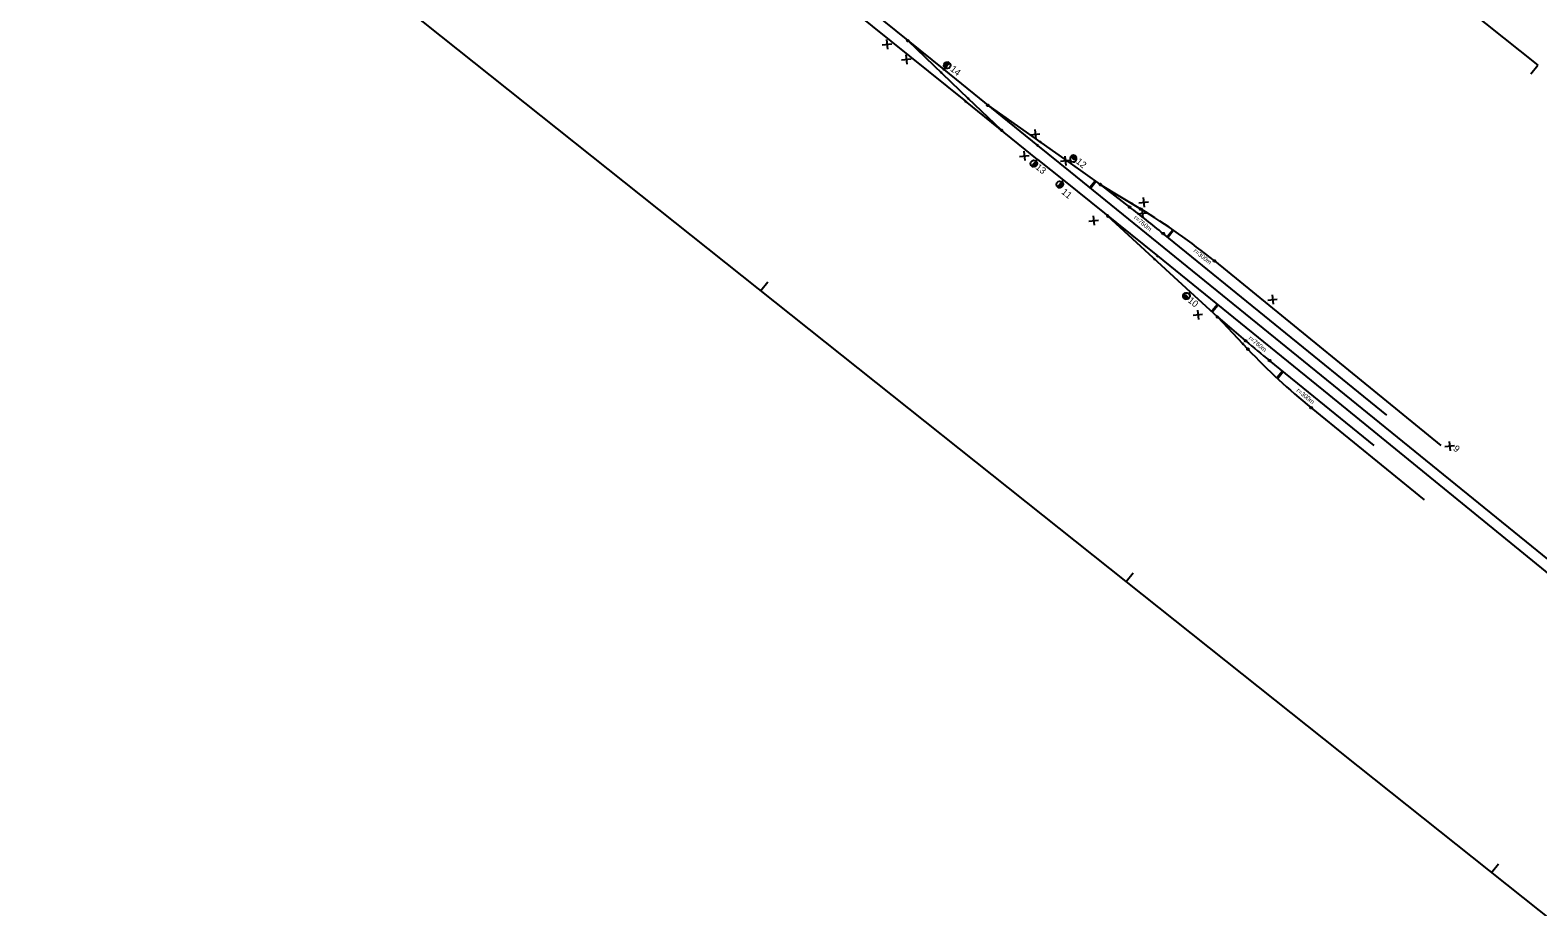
# Model space of a CAD drawing. Extents: x -481120 to -479270, y -1317564 to -1316014.
# Drawn here: x -481120 to -480442, y -1316785 to -1316391 of the extents above; entities that cross this region are included whole.
import ezdxf

# ---------------------------------------------------------------- set-up
doc = ezdxf.new("R2010")
doc.units = 0
for name, color, linetype in [('kolaj s', 7, 'Continuous'), ('Level 61', 7, 'Continuous'), ('popis 25', 7, 'Continuous'), ('popis 35', 7, 'Continuous')]:
    doc.layers.add(name, color=color, linetype=linetype)

msp = doc.modelspace()

# ---------------------------------------------------------------- linework, layer by layer
at = {"layer": 'kolaj s'}
for p, q in [((-480888.64, -1316270.51), (-480699.16, -1316423.18)), ((-480741.34, -1316382.82), (-480709, -1316408.98)), ((-480725.17, -1316395.9), (-480725.17, -1316395.9)), ((-480725.17, -1316395.9), (-480698.02, -1316421.88)), ((-480708.7, -1316408.59), (-480709.3, -1316409.38)), ((-480709, -1316408.98), (-480709, -1316408.98)), ((-480709, -1316408.98), (-480666.85, -1316443.08)), ((-480709.8, -1316409.92), (-480710.49, -1316410.64)), ((-480710.14, -1316410.28), (-480710.14, -1316410.28)), ((-480699.47, -1316423.57), (-480698.85, -1316422.79)), ((-480698.36, -1316422.24), (-480697.67, -1316421.52)), ((-480682.99, -1316436.26), (-480698.02, -1316421.88)), ((-480698.02, -1316421.88), (-480698.02, -1316421.88)), ((-480666.82, -1316449.34), (-480699.16, -1316423.18)), ((-480699.16, -1316423.18), (-480699.16, -1316423.18)), ((-480689.2, -1316425), (-480689.2, -1316425)), ((-480689.2, -1316425), (-480652.2, -1316451.04)), ((-480682.99, -1316436.26), (-480682.99, -1316436.26)), ((-480666.54, -1316442.69), (-480667.17, -1316443.47)), ((-480666.85, -1316443.08), (-480652.11, -1316455)), ((-480666.85, -1316443.08), (-480666.85, -1316443.08)), ((-480665.4, -1316441.14), (-480665.98, -1316441.95)), ((-480665.69, -1316441.54), (-480665.69, -1316441.54)), ((-480666.82, -1316449.34), (-480655.14, -1316458.74)), ((-480652.2, -1316451.04), (-480638.61, -1316460.6)), ((-480652.11, -1316455), (-480403.35, -1316656.97)), ((-480655.14, -1316458.74), (-480612.91, -1316492.74)), ((-480638.61, -1316460.6), (-480638.61, -1316460.6)), ((-480638.61, -1316460.6), (-480620.49, -1316471.62)), ((-480638.61, -1316460.6), (-480625.45, -1316470.75)), ((-480625.15, -1316470.35), (-480625.76, -1316471.14)), ((-480624.15, -1316468.81), (-480624.67, -1316469.66)), ((-480624.41, -1316469.23), (-480624.41, -1316469.23)), ((-480635.3, -1316474.72), (-480598.2, -1316508.93)), ((-480635.3, -1316474.72), (-480635.3, -1316474.72)), ((-480625.45, -1316470.75), (-480625.45, -1316470.75)), ((-480625.45, -1316470.75), (-480625.45, -1316470.75)), ((-480620.49, -1316471.62), (-480620.49, -1316471.62)), ((-480610.31, -1316482.74), (-480509.95, -1316564.28)), ((-480610.31, -1316482.74), (-480610.31, -1316482.74)), ((-480614.51, -1316494.57), (-480613.83, -1316493.83)), ((-480614.17, -1316494.2), (-480614.17, -1316494.2)), ((-480613.22, -1316493.13), (-480612.6, -1316492.35)), ((-480612.91, -1316492.74), (-480612.91, -1316492.74)), ((-480612.91, -1316492.74), (-480535.94, -1316555.28)), ((-480587.3, -1316495.01), (-480485.45, -1316578.03)), ((-480587.3, -1316495.01), (-480587.3, -1316495.01)), ((-480598.2, -1316508.93), (-480585.98, -1316520.2)), ((-480585.98, -1316520.19), (-480585.98, -1316520.19)), ((-480585.98, -1316520.19), (-480572.26, -1316534.66)), ((-480585.98, -1316520.19), (-480573.29, -1316530.91)), ((-480572.96, -1316530.53), (-480573.61, -1316531.29)), ((-480573.29, -1316530.91), (-480573.29, -1316530.91)), ((-480573.28, -1316530.92), (-480573.28, -1316530.92)), ((-480574.19, -1316531.9), (-480574.91, -1316532.59)), ((-480574.19, -1316531.9), (-480574.91, -1316532.59)), ((-480574.55, -1316532.25), (-480574.55, -1316532.25)), ((-480574.55, -1316532.25), (-480574.55, -1316532.25)), ((-480572.26, -1316534.66), (-480572.26, -1316534.66)), ((-480515.51, -1316578.06), (-480562.53, -1316539.83)), ((-480562.53, -1316539.83), (-480562.53, -1316539.83)), ((-480535.94, -1316555.28), (-480406.36, -1316660.81)), ((-480543.8, -1316561.02), (-480492.95, -1316602.35)), ((-480543.8, -1316561.02), (-480543.8, -1316561.02))]:
    msp.add_line(p, q, dxfattribs=at)
for points in [[(-480724.86, -1316396.16), (-480725.23, -1316396.3), (-480725.54, -1316396.05), (-480725.48, -1316395.65), (-480725.1, -1316395.51), (-480724.79, -1316395.76), (-480724.86, -1316396.16)], [(-480689.43, -1316425.33), (-480689.6, -1316424.97), (-480689.37, -1316424.64), (-480688.97, -1316424.68), (-480688.8, -1316425.04), (-480689.03, -1316425.37), (-480689.43, -1316425.33)], [(-480683.3, -1316436.01), (-480682.93, -1316435.87), (-480682.62, -1316436.12), (-480682.68, -1316436.51), (-480683.06, -1316436.65), (-480683.36, -1316436.4), (-480683.3, -1316436.01)], [(-480638.29, -1316460.84), (-480638.66, -1316461), (-480638.98, -1316460.75), (-480638.93, -1316460.36), (-480638.56, -1316460.2), (-480638.24, -1316460.45), (-480638.29, -1316460.84)], [(-480625.2, -1316470.44), (-480625.05, -1316470.81), (-480625.29, -1316471.12), (-480625.69, -1316471.07), (-480625.84, -1316470.7), (-480625.6, -1316470.38), (-480625.2, -1316470.44)], [(-480635.03, -1316474.42), (-480635.42, -1316474.34), (-480635.69, -1316474.63), (-480635.57, -1316475.01), (-480635.18, -1316475.1), (-480634.91, -1316474.81), (-480635.03, -1316474.42)], [(-480620.28, -1316471.28), (-480620.09, -1316471.62), (-480620.3, -1316471.96), (-480620.7, -1316471.96), (-480620.89, -1316471.61), (-480620.69, -1316471.27), (-480620.28, -1316471.28)], [(-480610.56, -1316483.05), (-480610.7, -1316482.68), (-480610.45, -1316482.37), (-480610.05, -1316482.43), (-480609.91, -1316482.8), (-480610.16, -1316483.11), (-480610.56, -1316483.05)], [(-480587.55, -1316495.32), (-480587.7, -1316494.95), (-480587.44, -1316494.64), (-480587.05, -1316494.7), (-480586.91, -1316495.07), (-480587.16, -1316495.38), (-480587.55, -1316495.32)], [(-480585.68, -1316520.45), (-480586.05, -1316520.58), (-480586.36, -1316520.33), (-480586.29, -1316519.93), (-480585.91, -1316519.8), (-480585.61, -1316520.06), (-480585.68, -1316520.45)], [(-480573.02, -1316530.61), (-480572.89, -1316530.99), (-480573.14, -1316531.29), (-480573.54, -1316531.22), (-480573.67, -1316530.84), (-480573.42, -1316530.54), (-480573.02, -1316530.61)], [(-480571.97, -1316534.39), (-480571.88, -1316534.77), (-480572.16, -1316535.05), (-480572.55, -1316534.94), (-480572.64, -1316534.55), (-480572.35, -1316534.27), (-480571.97, -1316534.39)], [(-480562.78, -1316540.14), (-480562.92, -1316539.76), (-480562.67, -1316539.45), (-480562.27, -1316539.52), (-480562.13, -1316539.89), (-480562.38, -1316540.2), (-480562.78, -1316540.14)], [(-480544.05, -1316561.33), (-480544.2, -1316560.96), (-480543.95, -1316560.65), (-480543.55, -1316560.71), (-480543.41, -1316561.08), (-480543.66, -1316561.39), (-480544.05, -1316561.33)]]:
    msp.add_lwpolyline(points, dxfattribs=at)
for centre, radius, start, end in [((-481089.57, -1317072.58), 760, 50.90503, 52.36083), ((-480776.33, -1316727.97), 300, 50.94386, 58.70492), ((-480083.02, -1315950.19), 760, 229.82799, 230.88077), ((-480354.59, -1316328.21), 300, 223.48502, 230.89789)]:
    msp.add_arc(centre, radius, start, end, dxfattribs=at)
at = {"layer": 'Level 61'}
for p, q in [((-480934.65, -1316014.34), (-480441.9, -1316406.9)), ((-480626.96, -1316639.2), (-481119.71, -1316246.64)), ((-480445.02, -1316410.81), (-480441.9, -1316406.9)), ((-480791.21, -1316508.34), (-480788.1, -1316504.43)), ((-480626.96, -1316639.2), (-480623.85, -1316635.28)), ((-479477.22, -1317555.16), (-480626.96, -1316639.2)), ((-480462.72, -1316770.05), (-480459.6, -1316766.14))]:
    msp.add_line(p, q, dxfattribs=at)
at = {"layer": 'popis 25'}
for p, q in [((-480641.07, -1316459.25), (-480643.26, -1316461.98)), ((-480640.71, -1316459.54), (-480642.9, -1316462.27)), ((-480606.21, -1316481.24), (-480608.4, -1316483.97)), ((-480605.85, -1316481.52), (-480608.04, -1316484.25)), ((-480586.12, -1316514.77), (-480588.31, -1316517.5)), ((-480585.77, -1316515.06), (-480587.96, -1316517.79)), ((-480556.86, -1316544.72), (-480559.05, -1316547.45)), ((-480556.5, -1316545.01), (-480558.69, -1316547.74))]:
    msp.add_line(p, q, dxfattribs=at)
at = {"layer": 'popis 35'}
for p, q in [((-480734.73, -1316395.44), (-480734.29, -1316399.69)), ((-480736.64, -1316397.78), (-480732.38, -1316397.34)), ((-480726.03, -1316402.28), (-480725.58, -1316406.53)), ((-480727.93, -1316404.62), (-480723.68, -1316404.18)), ((-480709, -1316408.98), (-480706.51, -1316405.91)), ((-480709, -1316408.98), (-480709, -1316408.98)), ((-480668.07, -1316435.92), (-480667.63, -1316440.17)), ((-480669.98, -1316438.26), (-480665.73, -1316437.82)), ((-480674.87, -1316448), (-480670.61, -1316447.56)), ((-480672.96, -1316445.65), (-480672.52, -1316449.9)), ((-480666.82, -1316449.34), (-480669.46, -1316452.28)), ((-480666.82, -1316449.34), (-480666.82, -1316449.34)), ((-480656.52, -1316450.18), (-480652.27, -1316449.74)), ((-480654.61, -1316447.83), (-480654.17, -1316452.09)), ((-480651.99, -1316448.13), (-480652.23, -1316448.82)), ((-480652.23, -1316448.82), (-480652.14, -1316449.57)), ((-480652.2, -1316451.04), (-480651.62, -1316450.22)), ((-480652.14, -1316449.57), (-480651.62, -1316450.22)), ((-480651.38, -1316447.65), (-480651.99, -1316448.13)), ((-480651.62, -1316450.22), (-480650.84, -1316450.5)), ((-480650.68, -1316447.48), (-480651.38, -1316447.65)), ((-480651.37, -1316448.3), (-480650.98, -1316447.74)), ((-480650.62, -1316447.75), (-480651.23, -1316448.61)), ((-480651.03, -1316448.86), (-480650.32, -1316447.84)), ((-480650.98, -1316447.74), (-480650.62, -1316447.75)), ((-480649.9, -1316447.77), (-480650.81, -1316449.06)), ((-480649.9, -1316447.77), (-480650.81, -1316449.06)), ((-480649.9, -1316447.77), (-480650.68, -1316447.48)), ((-480650.54, -1316449.21), (-480649.82, -1316448.19)), ((-480650.32, -1316447.84), (-480649.9, -1316447.77)), ((-480649.64, -1316448.44), (-480650.24, -1316449.3)), ((-480650.09, -1316450.36), (-480649.53, -1316449.86)), ((-480649.37, -1316448.42), (-480649.9, -1316447.77)), ((-480649.9, -1316447.77), (-480649.37, -1316448.4)), ((-480649.82, -1316448.19), (-480649.9, -1316447.77)), ((-480649.9, -1316449.33), (-480649.51, -1316448.78)), ((-480649.51, -1316448.78), (-480649.64, -1316448.44)), ((-480649.53, -1316449.86), (-480649.25, -1316449.14)), ((-480649.25, -1316449.14), (-480649.37, -1316448.42)), ((-480650.84, -1316450.5), (-480650.09, -1316450.36)), ((-480655.14, -1316458.74), (-480657.78, -1316461.68)), ((-480655.14, -1316458.74), (-480655.14, -1316458.74)), ((-480621.24, -1316468.85), (-480616.98, -1316468.4)), ((-480619.33, -1316466.5), (-480618.89, -1316470.75)), ((-480643.72, -1316477.06), (-480639.47, -1316476.61)), ((-480641.82, -1316474.71), (-480641.38, -1316478.96)), ((-480621.89, -1316473.75), (-480617.64, -1316473.31)), ((-480619.99, -1316471.4), (-480619.54, -1316475.66)), ((-480601.35, -1316511.17), (-480601.34, -1316510.45)), ((-480600.91, -1316511.87), (-480601.35, -1316511.17)), ((-480601.34, -1316510.45), (-480601, -1316509.75)), ((-480600.7, -1316510.32), (-480601.16, -1316510.82)), ((-480601.16, -1316510.82), (-480601.08, -1316511.17)), ((-480601.08, -1316511.17), (-480600.36, -1316510.39)), ((-480601, -1316509.75), (-480600.37, -1316509.37)), ((-480600.08, -1316510.53), (-480600.93, -1316511.44)), ((-480600.91, -1316511.87), (-480599.84, -1316510.71)), ((-480600.91, -1316511.87), (-480599.84, -1316510.71)), ((-480599.64, -1316510.93), (-480600.49, -1316511.85)), ((-480600.37, -1316509.37), (-480599.63, -1316509.29)), ((-480600.2, -1316511.98), (-480599.48, -1316511.21)), ((-480599.63, -1316509.29), (-480598.88, -1316509.66)), ((-480598.88, -1316509.66), (-480598.2, -1316508.93)), ((-480598.88, -1316509.66), (-480598.43, -1316510.37)), ((-480598.42, -1316511.13), (-480598.79, -1316511.78)), ((-480598.43, -1316510.37), (-480598.42, -1316511.13)), ((-480561.41, -1316510.22), (-480560.96, -1316514.47)), ((-480600.93, -1316511.44), (-480600.91, -1316511.87)), ((-480600.49, -1316511.85), (-480600.91, -1316511.87)), ((-480600.16, -1316512.25), (-480600.91, -1316511.87)), ((-480600.91, -1316511.87), (-480600.18, -1316512.25)), ((-480599.84, -1316512.04), (-480600.2, -1316511.98)), ((-480599.43, -1316512.21), (-480600.16, -1316512.25)), ((-480599.38, -1316511.54), (-480599.84, -1316512.04)), ((-480598.79, -1316511.78), (-480599.43, -1316512.21)), ((-480594.96, -1316517.1), (-480594.52, -1316521.35)), ((-480563.31, -1316512.57), (-480559.06, -1316512.12)), ((-480596.87, -1316519.44), (-480592.62, -1316519)), ((-480483.65, -1316578.49), (-480479.39, -1316578.05)), ((-480481.74, -1316576.15), (-480481.3, -1316580.4))]:
    msp.add_line(p, q, dxfattribs=at)
for points in [[(-480706.83, -1316405.66), (-480706.2, -1316406.16), (-480705.93, -1316406.91), (-480706.06, -1316407.65), (-480706.55, -1316408.25), (-480707.27, -1316408.53), (-480708.03, -1316408.42), (-480708.65, -1316407.92), (-480708.92, -1316407.2), (-480708.81, -1316406.44), (-480708.3, -1316405.82), (-480707.58, -1316405.55), (-480706.83, -1316405.66), (-480707.18, -1316405.7), (-480706.79, -1316406.01), (-480706.98, -1316406.25), (-480707.64, -1316405.71), (-480707.98, -1316405.82), (-480707.17, -1316406.48), (-480707.36, -1316406.71), (-480708.25, -1316405.99), (-480708.44, -1316406.22), (-480707.54, -1316406.95), (-480707.73, -1316407.18), (-480708.63, -1316406.46), (-480708.7, -1316406.78), (-480707.92, -1316407.41), (-480708.11, -1316407.65), (-480708.77, -1316407.11), (-480708.69, -1316407.56), (-480708.3, -1316407.88)], [(-480669.17, -1316452.54), (-480669.76, -1316452.01), (-480669.99, -1316451.25), (-480669.84, -1316450.53), (-480669.3, -1316449.93), (-480668.57, -1316449.7), (-480667.82, -1316449.85), (-480667.23, -1316450.39), (-480666.99, -1316451.12), (-480667.16, -1316451.88), (-480667.67, -1316452.46), (-480668.41, -1316452.7), (-480669.17, -1316452.54), (-480668.81, -1316452.53), (-480669.18, -1316452.19), (-480668.98, -1316451.97), (-480668.35, -1316452.54), (-480668.04, -1316452.41), (-480668.78, -1316451.74), (-480668.58, -1316451.52), (-480667.73, -1316452.29), (-480667.53, -1316452.07), (-480668.38, -1316451.3), (-480668.18, -1316451.08), (-480667.33, -1316451.84), (-480667.24, -1316451.52), (-480667.98, -1316450.85), (-480667.78, -1316450.63), (-480667.18, -1316451.16), (-480667.24, -1316450.71), (-480667.58, -1316450.41)], [(-480657.49, -1316461.94), (-480658.08, -1316461.41), (-480658.31, -1316460.65), (-480658.16, -1316459.93), (-480657.62, -1316459.33), (-480656.89, -1316459.1), (-480656.14, -1316459.26), (-480655.55, -1316459.79), (-480655.31, -1316460.52), (-480655.48, -1316461.28), (-480656, -1316461.86), (-480656.74, -1316462.1), (-480657.49, -1316461.94), (-480657.13, -1316461.93), (-480657.51, -1316461.59), (-480657.3, -1316461.37), (-480656.67, -1316461.94), (-480656.36, -1316461.82), (-480657.1, -1316461.15), (-480656.9, -1316460.92), (-480656.05, -1316461.69), (-480655.85, -1316461.47), (-480656.7, -1316460.7), (-480656.5, -1316460.48), (-480655.65, -1316461.25), (-480655.56, -1316460.92), (-480656.3, -1316460.26), (-480656.1, -1316460.03), (-480655.5, -1316460.57), (-480655.56, -1316460.11), (-480655.9, -1316459.81)]]:
    msp.add_lwpolyline(points, dxfattribs=at)
for centre, start, end in [((-480649.94, -1316447.83), 173.09262, 296.63748), ((-480600.85, -1316511.81), 345.54433, 109.08919)]:
    msp.add_arc(centre, 1.5, start, end, dxfattribs=at)

# ---------------------------------------------------------------- texts
at = {"layer": 'popis 25'}
for s, p in [('r=760m', (-480623.72, -1316475.84)), ('r=300m', (-480596.89, -1316490.78)), ('r=760m', (-480572.13, -1316530.08)), ('r=300m', (-480550.64, -1316553.56))]:
    msp.add_text(s, height=2, rotation=320.75676, dxfattribs=at).set_placement(p)
at = {"layer": 'popis 35'}
for s, p in [('14', (-480706.33, -1316409.19)), ('12', (-480649.8, -1316450.76)), ('13', (-480667.97, -1316453.35)), ('11', (-480656.33, -1316464.46)), ('10', (-480599.51, -1316513.25)), ('9', (-480480.22, -1316579.87))]:
    msp.add_text(s, height=3, rotation=320.95676, dxfattribs=at).set_placement(p)

doc.saveas('drawing.dxf')
